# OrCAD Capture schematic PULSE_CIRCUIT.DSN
size A
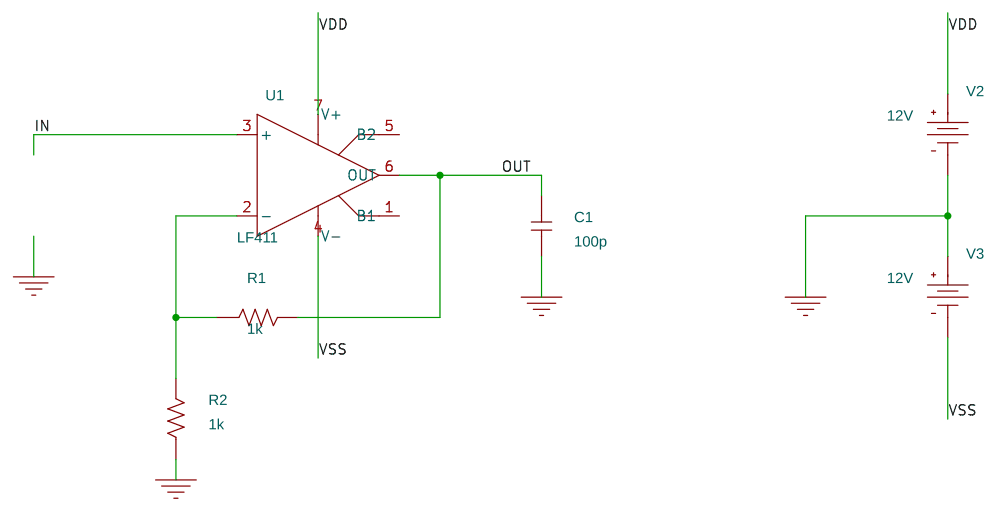
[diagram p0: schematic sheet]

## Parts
C1  100p  [cap196]
R1  1k  [AXRC05]
R2  1k  [AXRC05]
U1  LF411  [DIP1008W300L450]
V2  VDC
V3  VDC

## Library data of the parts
C1 = C
R1 R2 = R
U1 = LF411
V2 V3 = VDC: DC: 12V

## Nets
VDD: U1.7(V+) V2.0(+)
VSS: U1.4(V-) V3.1(-)
0: C1.1 R2.1 V2.1(-) V3.0(+)
IN: U1.3(+)
OUT: C1.2 R1.2 U1.6(OUT)
N00123: R1.1 R2.2 U1.2(-)

Not connected (* = marked no-connect by the designer): U1 1(B1) 5(B2)
